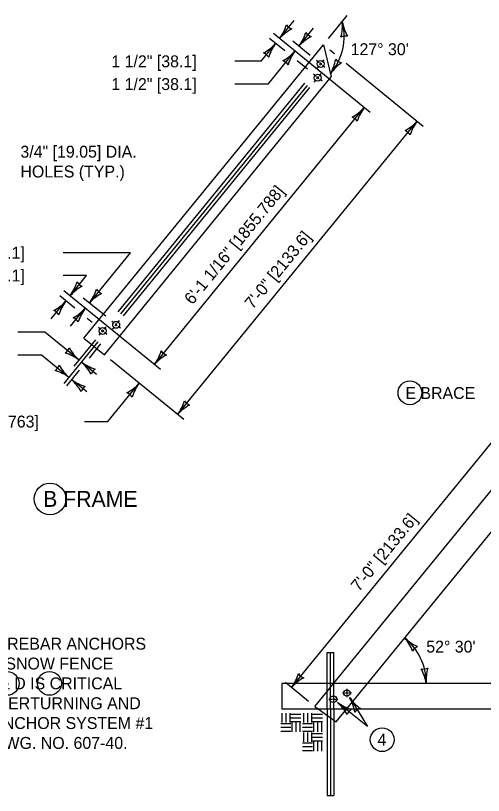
# Model space of a CAD drawing. Extents: x 49991.4 to 50021, y 49987.6 to 50011.4.
# Drawn here: x 50009.55 to 50011.907, y 49992.911 to 49996.841 of the extents above; entities that cross this region are included whole.
import ezdxf

# ---------------------------------------------------------------- set-up
doc = ezdxf.new("R2010")
doc.units = 0
for name, color, linetype in [('Level 1', 7, 'Continuous'), ('Level 2', 7, 'Continuous'), ('Level 3', 7, 'Continuous'), ('Level 4', 7, 'Continuous'), ('Level 5', 7, 'Continuous')]:
    doc.layers.add(name, color=color, linetype=linetype)

msp = doc.modelspace()

# ---------------------------------------------------------------- linework, layer by layer
at = {"layer": 'Level 1'}
for p, q in [((50009.8947, 49995.2149), (50011.1021, 49996.6944)), ((50011.1021, 49996.6944), (50011.1404, 49996.5316)), ((50009.9976, 49995.1309), (50011.1404, 49996.5316)), ((50010.0677, 49995.3481), (50011.0079, 49996.4999)), ((50010.0805, 49995.3377), (50011.0207, 49996.4895)), ((50010.0935, 49995.3271), (50011.0335, 49996.4791)), ((50011.1535, 49993.4768), (50013.1083, 49995.8723)), ((50011.2191, 49993.3474), (50013.1526, 49995.7167)), ((50009.8947, 49995.2149), (50009.9976, 49995.1309)), ((50009.8949, 49995.215), (50009.8949, 49995.215)), ((50011.1195, 49993.3474), (50011.1195, 49993.6302)), ((50011.1195, 49993.6302), (50011.1535, 49993.6302)), ((50011.1364, 49993.3474), (50011.1364, 49993.6302)), ((50011.1535, 49993.3474), (50011.1535, 49993.6302)), ((50011.1535, 49993.3474), (50011.1535, 49993.5474)), ((50010.8912, 49993.4751), (50010.8912, 49993.3474)), ((50013.6869, 49993.4751), (50010.8912, 49993.4751)), ((50011.1535, 49993.3474), (50011.1535, 49993.4751)), ((50011.0576, 49993.3593), (50011.1195, 49993.4351)), ((50010.8912, 49993.3474), (50013.6869, 49993.3474)), ((50011.0576, 49993.3593), (50011.0742, 49993.3474)), ((50010.8922, 49993.325), (50010.8922, 49993.2777)), ((50010.9123, 49993.325), (50010.9123, 49993.2777)), ((50010.9323, 49993.325), (50010.9323, 49993.2777)), ((50010.9371, 49993.3206), (50010.9874, 49993.3206)), ((50010.9371, 49993.3017), (50010.9874, 49993.3017)), ((50011.0016, 49993.325), (50011.0016, 49993.2777)), ((50011.0218, 49993.325), (50011.0218, 49993.2777)), ((50011.0419, 49993.325), (50011.0419, 49993.2777)), ((50011.0466, 49993.3206), (50011.0969, 49993.3206)), ((50011.0466, 49993.3017), (50011.0969, 49993.3017)), ((50010.8867, 49993.2733), (50010.9371, 49993.2733)), ((50010.9371, 49993.2827), (50010.9874, 49993.2827)), ((50010.9421, 49993.2781), (50010.9421, 49993.2307)), ((50010.9622, 49993.2781), (50010.9622, 49993.2307)), ((50010.9824, 49993.2781), (50010.9824, 49993.2307)), ((50010.9962, 49993.2733), (50011.0466, 49993.2733)), ((50011.0466, 49993.2827), (50011.0969, 49993.2827)), ((50011.0517, 49993.2781), (50011.0517, 49993.2307)), ((50011.0717, 49993.2781), (50011.0717, 49993.2307)), ((50011.0918, 49993.2781), (50011.0918, 49993.2307)), ((50010.8867, 49993.2544), (50010.9371, 49993.2544)), ((50010.8867, 49993.2353), (50010.9371, 49993.2353)), ((50010.9962, 49993.2544), (50011.0466, 49993.2544)), ((50010.9962, 49993.2353), (50011.0466, 49993.2353)), ((50011.0016, 49993.2275), (50011.0016, 49993.1802)), ((50011.0218, 49993.2275), (50011.0218, 49993.1802)), ((50011.0419, 49993.2275), (50011.0419, 49993.1802)), ((50011.0466, 49993.2231), (50011.0969, 49993.2231)), ((50011.0466, 49993.2041), (50011.0969, 49993.2041)), ((50011.0466, 49993.1853), (50011.0969, 49993.1853)), ((50011.0517, 49993.1804), (50011.0517, 49993.1331)), ((50011.0717, 49993.1804), (50011.0717, 49993.1331)), ((50011.0918, 49993.1804), (50011.0918, 49993.1331)), ((50010.9962, 49993.1758), (50011.0466, 49993.1758)), ((50010.9962, 49993.1568), (50011.0466, 49993.1568)), ((50010.9962, 49993.1378), (50011.0466, 49993.1378))]:
    msp.add_line(p, q, dxfattribs=at)
for centre in [(50011.0874, 49996.5973), (50011.0729, 49996.5275), (50009.9888, 49995.2514), (50010.0571, 49995.2825)]:
    msp.add_circle(centre, 0.0175, dxfattribs=at)
for centre in [(50011.2198, 49993.4269), (50011.1515, 49993.3957)]:
    msp.add_ellipse(centre, major_axis=(0.017, 0), ratio=0.940299, dxfattribs=at)
at = {"layer": 'Level 2'}
for centre, radius in [((50011.5374, 49994.94), 0.06), ((50009.724, 49994.4051), 0.08), ((50009.5076, 49993.4753), 0.06), ((50009.7212, 49993.4753), 0.06), ((50011.3976, 49993.1916), 0.06)]:
    msp.add_circle(centre, radius, dxfattribs=at)
at = {"layer": 'Level 3'}
for p, q in [((50011.1274, 49996.7254), (50011.2218, 49996.841)), ((50010.8806, 49996.7254), (50010.9542, 49996.8157)), ((50010.978, 49996.6867), (50011.0517, 49996.7771)), ((50010.9072, 49996.663), (50010.8296, 49996.7262)), ((50011.3377, 49996.3525), (50010.8496, 49996.7507)), ((50010.7869, 49996.6105), (50010.8606, 49996.7009)), ((50011.0351, 49996.6401), (50010.9471, 49996.712)), ((50010.8224, 49996.4957), (50010.9581, 49996.6622)), ((50011.1331, 49996.6691), (50011.1574, 49996.6493)), ((50010.7869, 49996.6105), (50010.6549, 49996.6105)), ((50011.0206, 49996.5703), (50010.9691, 49996.6124)), ((50011.2165, 49996.601), (50011.6047, 49996.2843)), ((50010.8224, 49996.4957), (50010.6549, 49996.4957)), ((50010.2494, 49995.0821), (50011.3067, 49996.3778)), ((50010.3662, 49994.8299), (50011.5737, 49996.3096)), ((50010.1292, 49995.6457), (50009.7893, 49995.6457)), ((50009.9226, 49995.3923), (50010.1292, 49995.6457)), ((50009.908, 49995.5309), (50009.7893, 49995.5309)), ((50009.8248, 49995.4288), (50009.908, 49995.5309)), ((50009.8492, 49995.3657), (50009.7727, 49995.4282)), ((50010.2804, 49995.0568), (50009.7939, 49995.4541)), ((50009.7299, 49995.3124), (50009.8037, 49995.4029)), ((50010.0048, 49995.3253), (50009.8916, 49995.4176)), ((50009.8277, 49995.2759), (50009.9014, 49995.3663)), ((50009.9365, 49995.2942), (50009.9112, 49995.315)), ((50009.698, 49995.2451), (50009.5619, 49995.2451)), ((50009.8693, 49995.1052), (50009.698, 49995.2451)), ((50009.9652, 49995.1964), (50009.7937, 49994.9864)), ((50009.9524, 49995.2069), (50009.844, 49995.0743)), ((50009.9781, 49995.1859), (50009.9204, 49995.1151)), ((50009.6806, 49995.1303), (50009.5619, 49995.1303)), ((50009.819, 49995.0173), (50009.6806, 49995.1303)), ((50009.9588, 49995.0321), (50009.8822, 49995.0947)), ((50010.3972, 49994.8046), (50010.0286, 49995.1056)), ((50009.8699, 49995.0531), (50009.8067, 49994.9758)), ((50009.9086, 49994.9441), (50009.832, 49995.0067)), ((50010.0155, 49994.7949), (50010.1726, 49994.988)), ((50010.9407, 49993.4547), (50012.0697, 49994.8379)), ((50009.8969, 49994.7949), (50010.0155, 49994.7949)), ((50011.0266, 49993.3846), (50010.9098, 49993.48)), ((50011.3232, 49993.2581), (50011.1723, 49993.3791)), ((50011.2336, 49993.4046), (50011.3232, 49993.2581))]:
    msp.add_line(p, q, dxfattribs=at)
for centre, radius, start, end in [((50010.975, 49996.7909), 0.2223, 344.7387, 4.9222), ((50011.4259, 49996.8509), 0.233, 190.11, 209.3598), ((50010.693, 49996.8635), 0.233, 323.6452, 342.895), ((50011.047, 49996.578), 0.2223, 118.2739, 138.4574), ((50010.9616, 49996.8248), 0.0548, 212.9567, 248.6791), ((50010.7904, 49996.8249), 0.233, 323.6381, 342.888), ((50011.1444, 49996.5393), 0.2223, 118.2668, 138.4503), ((50011.059, 49996.7861), 0.0548, 212.9496, 248.672), ((50011.2128, 49996.6828), 0.0548, 79.4215, 115.1439), ((50010.6942, 49996.8484), 0.2223, 298.2668, 318.4503), ((50011.0483, 49996.5628), 0.233, 143.6381, 162.888), ((50010.7796, 49996.6016), 0.0548, 32.9496, 68.672), ((50010.7917, 49996.8096), 0.2223, 298.2672, 318.4507), ((50011.1457, 49996.5241), 0.233, 143.6385, 162.8883), ((50010.8771, 49996.5628), 0.0548, 32.95, 68.6724), ((50010.9341, 49996.6626), 0.233, 330.392, 349.6419), ((50011.3192, 49996.4207), 0.2223, 125.0207, 145.2042), ((50011.2054, 49996.6557), 0.0548, 219.7035, 255.4259), ((50011.1404, 49996.5253), 0.2223, 298.2386, 318.4221), ((50011.4943, 49996.2395), 0.233, 143.6099, 162.8597), ((50011.2257, 49996.2784), 0.0548, 32.9214, 68.6437), ((50011.4074, 49996.4571), 0.2223, 298.2384, 318.4219), ((50011.7613, 49996.1713), 0.233, 143.6097, 162.8595), ((50011.4927, 49996.2102), 0.0548, 32.9212, 68.6435), ((50009.6372, 49995.5669), 0.233, 323.6512, 342.901), ((50009.9912, 49995.2814), 0.2223, 118.2799, 138.4634), ((50009.9058, 49995.5282), 0.0548, 212.9627, 248.685), ((50009.735, 49995.5305), 0.233, 323.6365, 342.8864), ((50010.0036, 49995.4917), 0.0548, 212.9481, 248.6704), ((50010.089, 49995.2449), 0.2223, 118.2652, 138.4488), ((50009.6373, 49995.5503), 0.2223, 298.2668, 318.4503), ((50009.9913, 49995.2647), 0.233, 143.6381, 162.888), ((50009.7227, 49995.3035), 0.0548, 32.9496, 68.672), ((50009.735, 49995.5138), 0.2223, 298.2668, 318.4503), ((50010.089, 49995.2282), 0.233, 143.6381, 162.888), ((50009.8204, 49995.2669), 0.0548, 32.9496, 68.672), ((50009.77, 49995.1863), 0.0548, 302.8992, 338.6215), ((50010.0169, 49995.2715), 0.2223, 208.2164, 228.3999), ((50010.0618, 49995.2203), 0.233, 323.6097, 342.8595), ((50010.3305, 49995.1814), 0.0548, 212.9212, 248.6435), ((50009.731, 49994.9177), 0.233, 53.5877, 72.8375), ((50010.4157, 49994.9346), 0.2223, 118.2384, 138.4219), ((50009.7196, 49995.0984), 0.0548, 302.9081, 338.6304), ((50009.9665, 49995.1836), 0.2223, 208.2253, 228.4088), ((50009.7345, 49994.9285), 0.2223, 28.1992, 48.3827), ((50010.0205, 49995.2822), 0.233, 233.5705, 252.8204), ((50009.6807, 49994.8298), 0.233, 53.5966, 72.8464), ((50009.9814, 49995.0136), 0.0548, 122.882, 158.6044), ((50009.6843, 49994.8405), 0.2223, 28.1992, 48.3827), ((50009.9703, 49995.1942), 0.233, 233.5705, 252.8204), ((50009.9313, 49994.9256), 0.0548, 122.882, 158.6044), ((50010.0062, 49995.1354), 0.2223, 298.2824, 318.4659), ((50010.3603, 49994.8499), 0.233, 143.6537, 162.9035), ((50010.0916, 49994.8886), 0.0548, 32.9652, 68.6875), ((50010.1786, 49994.9681), 0.233, 323.6092, 342.859), ((50010.5325, 49994.6824), 0.2223, 118.2379, 138.4214), ((50010.4473, 49994.9292), 0.0548, 212.9207, 248.643), ((50011.3233, 49993.4751), 0.2966, 0, 50.7817), ((50011.3433, 49993.5586), 0.2223, 20.9437, 41.1272), ((50011.6717, 49993.8733), 0.233, 226.315, 245.5648), ((50011.599, 49993.6118), 0.0548, 115.6265, 151.3488), ((50011.6039, 49993.6023), 0.0548, 259.3026, 295.025), ((50011.3904, 49993.4347), 0.233, 9.9911, 29.241), ((50011.8414, 49993.4937), 0.2223, 164.6198, 184.8033), ((50010.7532, 49993.593), 0.233, 323.6052, 342.855), ((50011.107, 49993.3072), 0.2223, 118.2339, 138.4174), ((50011.0218, 49993.5541), 0.0548, 212.9167, 248.6391), ((50011.0262, 49993.2115), 0.2223, 28.7314, 48.9149), ((50011.3089, 49993.5678), 0.233, 234.1027, 253.3526), ((50011.0393, 49993.2965), 0.2223, 8.9061, 29.0896), ((50011.4261, 49993.5358), 0.233, 214.2774, 233.5273), ((50011.2723, 49993.2989), 0.0548, 123.4142, 159.1366), ((50011.3005, 49993.2952), 0.0548, 103.5889, 139.3113)]:
    msp.add_arc(centre, radius, start, end, dxfattribs=at)
msp.add_ellipse((50010.8775, 49996.7369), major_axis=(0.3284, 0), ratio=0.938809, start_param=5.621944, end_param=6.522718, dxfattribs=at)
at = {"layer": 'Level 4'}
for p, q in [((50011.1195, 49993.4351), (50011.1535, 49993.4768)), ((50011.0743, 49993.3474), (50011.1654, 49993.2816)), ((50011.1195, 49993.3474), (50011.1195, 49992.9107)), ((50011.1364, 49993.3474), (50011.1364, 49992.9107)), ((50011.1535, 49993.3474), (50011.1535, 49992.9107)), ((50011.1654, 49993.2816), (50011.2192, 49993.3474)), ((50011.1195, 49992.9107), (50011.1535, 49992.9107))]:
    msp.add_line(p, q, dxfattribs=at)
at = {"layer": 'Level 5'}
for p, q in [((50011.0777, 49996.6053), (50011.0661, 49996.6148)), ((50011.0932, 49996.5926), (50011.0816, 49996.6021)), ((50011.0827, 49996.5916), (50011.0922, 49996.6032)), ((50011.0954, 49996.6071), (50011.1049, 49996.6187)), ((50011.07, 49996.5761), (50011.0795, 49996.5877)), ((50011.1087, 49996.5799), (50011.0971, 49996.5894)), ((50011.0632, 49996.5355), (50011.0516, 49996.545)), ((50011.0787, 49996.5228), (50011.0671, 49996.5323)), ((50011.0682, 49996.5218), (50011.0777, 49996.5334)), ((50011.0809, 49996.5373), (50011.0904, 49996.5489)), ((50011.0555, 49996.5063), (50011.065, 49996.5179)), ((50011.0942, 49996.5101), (50011.0826, 49996.5196)), ((50010.0651, 49995.2923), (50010.0746, 49995.3039)), ((50009.9791, 49995.2594), (50009.9675, 49995.2689)), ((50009.9968, 49995.2612), (50010.0063, 49995.2728)), ((50010.0474, 49995.2905), (50010.0358, 49995.3)), ((50010.0397, 49995.2613), (50010.0492, 49995.2729)), ((50010.0629, 49995.2778), (50010.0513, 49995.2873)), ((50010.0524, 49995.2768), (50010.0619, 49995.2884)), ((50010.0784, 49995.2651), (50010.0668, 49995.2746)), ((50009.9714, 49995.2302), (50009.9809, 49995.2418)), ((50009.9946, 49995.2467), (50009.983, 49995.2562)), ((50009.9841, 49995.2457), (50009.9936, 49995.2573)), ((50010.0101, 49995.234), (50009.9985, 49995.2435)), ((50011.1514, 49993.4169), (50011.1514, 49993.4031)), ((50011.1971, 49993.4269), (50011.2118, 49993.4269)), ((50011.2154, 49993.4269), (50011.2248, 49993.4269)), ((50011.2197, 49993.4481), (50011.2197, 49993.4343)), ((50011.2197, 49993.432), (50011.2197, 49993.4228)), ((50011.2197, 49993.4194), (50011.2197, 49993.4056)), ((50011.2277, 49993.4269), (50011.2424, 49993.4269)), ((50011.1288, 49993.3957), (50011.1435, 49993.3957)), ((50011.1471, 49993.3957), (50011.1565, 49993.3957)), ((50011.1514, 49993.4008), (50011.1514, 49993.3916)), ((50011.1514, 49993.3882), (50011.1514, 49993.3744)), ((50011.1594, 49993.3957), (50011.1741, 49993.3957))]:
    msp.add_line(p, q, dxfattribs=at)

# ---------------------------------------------------------------- texts
at = {"layer": 'Level 2'}
for s, height, p in [("127° 30'", 0.06, (50011.2384, 49996.6416)), ('1 1/2" [38.1]', 0.06, (50010.0328, 49996.5805)), ('1 1/2" [38.1]', 0.06, (50010.0328, 49996.4657)), ('3/4" [19.05] DIA.', 0.06, (50009.5746, 49996.125)), ('HOLES (TYP.)', 0.06, (50009.5746, 49996.025)), ('1 1/2" [38.1]', 0.06, (50009.1672, 49995.6157)), ('1 1/2" [38.1]', 0.06, (50009.1672, 49995.5009)), ('E BRACE', 0.06, (50011.5143, 49994.9086)), ('5 3/16" [131.763]', 0.06, (50009.0593, 49994.7649)), ('B FRAME', 0.08, (50009.6893, 49994.3651)), ('PLACEMENT OF REBAR ANCHORS', 0.06, (50008.8615, 49993.6453)), ("52° 30'", 0.06, (50011.6195, 49993.6305)), ('TIGHT AGAINST SNOW FENCE', 0.06, (50008.8615, 49993.5453)), ('MEMBERS A  C & D IS CRITICAL', 0.06, (50008.8615, 49993.4453)), ('TO PREVENT OVERTURNING AND', 0.06, (50008.8615, 49993.3453)), ('SLIDING.  SEE ANCHOR SYSTEM #1', 0.06, (50008.8615, 49993.2453)), ('4', 0.06, (50011.3736, 49993.1616)), ('DETAILS, DTL. DWG. NO. 607-40.', 0.06, (50008.8615, 49993.1453))]:
    msp.add_text(s, height=height, dxfattribs=at).set_placement(p)
for s, rotation, p in [('6\'-1 1/16" [1855.788]', 50.7823, (50010.4411, 49995.3803)), ('7\'-0" [2133.6]', 50.7823, (50010.7453, 49995.3577)), ('7\'-0" [2133.6]', 50.7792, (50011.2806, 49993.9344))]:
    msp.add_text(s, height=0.06, rotation=rotation, dxfattribs=at).set_placement(p)

doc.saveas('drawing.dxf')
